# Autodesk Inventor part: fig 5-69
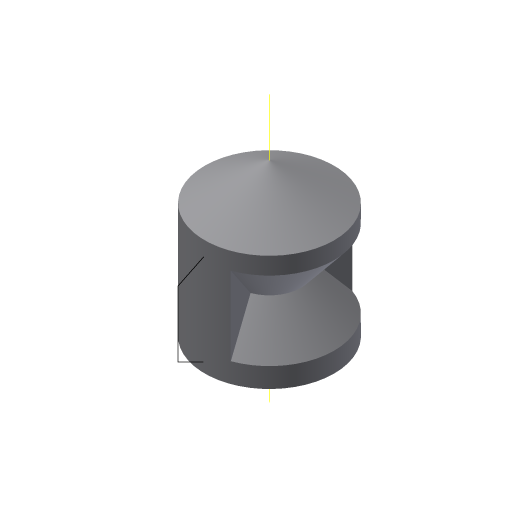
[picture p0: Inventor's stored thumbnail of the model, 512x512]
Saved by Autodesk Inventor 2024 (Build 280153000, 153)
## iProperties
Created: 2004-05
Part Number: fig 5-69
Document SubType Name: Modeling
Designer: CADCIM Technologies
Manufacturer: Standard
Standards Organization: Custom
Density: 1 g/cm^3
Material: Generic
Appearance: Default
Author: CADCIM Technologies
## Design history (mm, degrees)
sketch "Sketch1"
  geometry: L1 (0, -21.51)-(0, 21.51); L2 (0, 21.51)-(-14.639, 13.059); L3 (-14.639, 13.059)-(-14.639, -13.059); L4 (-14.639, -13.059)-(0, -21.51); 2 further points
  constraints: 8 end point, 1 coincident, 1 equal length, 1 midpoint, 1 parallel, 1 vertical, 1 other
  dimensions: "d3" = 120 deg angle of L4 L3
revolve "Revolution1" sketch "Sketch1" stored, may be unused: angle "d0" = 90 deg
workaxis "Work Axis1"
sketch "Sketch2"
  geometry: L1 (-15.658, 10.423)-(-7.144, 0); L2 (-7.144, 0)-(-15.658, -9.738); L3 (-15.658, -9.738)-(-15.658, 10.423); L4 (0, -25.812)-(0, 34.416) reference
  constraints: 6 end point, 1 vertical
revolve "Revolution2" sketch "Sketch2" stored, may be unused: angle "d4" = 140 deg
sketch "Sketch3"
  geometry: L1 (-14.955, 9.983)-(-20.736, 7.191); L2 (-20.736, 7.191)-(-20.736, -7.686); L3 (-20.736, -7.686)-(-15, -10.57); L4 (0, -25.812)-(0, 34.416) reference
  constraints: 6 end point, 1 equal length, 1 vertical
body "Solid1"
